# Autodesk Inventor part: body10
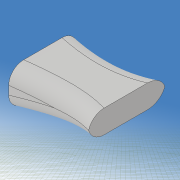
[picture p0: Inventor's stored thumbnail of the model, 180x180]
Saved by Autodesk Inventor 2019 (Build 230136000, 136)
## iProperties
Created: 2020-12
Part Number: body10
Material: 一般
Document SubType Name: Modeling
Designer: kikut
Density: 1 g/cm^3
Appearance: 既定
Mass: 87.6477 g
Surface Area: 156.124 cm^2
Volume: 87.6477 cm^3
Author: kikut
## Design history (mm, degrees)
sketch "スケッチ1"
  geometry: L1 (-100, -20)-(100, -20); L2 (100, -20)-(100, 20); L3 (100, 20)-(-100, 20); L4 (-100, 20)-(-100, -20); L5 (-100, -20)-(100, 20); L6 (100, -20)-(-100, 20); 1 further point
  constraints: 12 end point, 2 midpoint, 2 parallel, 1 horizontal, 1 perpendicular
  dimensions: "d0" = 40 distance of L3.end L1.start; "d1" = 200 distance of L2.end L3.end
extrude "押し出し1" new body sketch "スケッチ1" stored distance "d2" = 60; taper "d3" = 0 deg
sketch "スケッチ2"
  geometry: L1 (0, -60)-(0, 0) reference; L2 (200, -60)-(200, 0) reference; L3 (0, 0)-(200, 0) reference; L4 (200, -60)-(0, -60) reference; L5 (0, -26)-(0, -32); L6 (194, -10)-(194, -13); L7 (194, -13)-(174, -33); L8 (174, -33)-(200, -58); L9 (-20, 20)-(220, 20); L10 (220, 20)-(220, -100); L11 (220, -100)-(-20, -100); L12 (-20, -100)-(-20, 20); 12 further points
  constraints: 16 end point, 4 point on line, 2 parallel, 2 vertical, 1 horizontal, 1 perpendicular, 14 other
  dimensions: "d4" = 32 distance from line of point (32, -12) L1; "d5" = 50 horizontal distance of point (32, -12) point (82, -11); "d6" = 50 horizontal distance of point (132, -17) point (82, -11); "d7" = 12 distance from line of point (32, -12) L3; "d8" = 11 distance from line of point (82, -11) L3; "d10" = 17 distance from line of point (132, -17) L3; "d11" = 26 distance from line of L5.start L3; "d12" = 0 distance from line of point (200, -60) L4; "d13" = 28 distance from line of L5.end L4; "d14" = 12 distance from line of point (28, -48) L4; "d15" = 10 distance from line of point (80, -50) L4; "d16" = 16 distance from line of point (130, -44) L4; "d17" = 28 distance from line of point (28, -48) L1; "d19" = 50 horizontal distance of point (130, -44) point (80, -50); "d20" = 80 distance from line of point (80, -50) L1; "d21" = 6 distance from line of L6.start L2; "d22" = 36 distance from line of point (164, -24) L2; "d23" = 24 distance from line of point (176, -20) L2; "d24" = 10 distance from line of L6.start L3; "d25" = 20 distance from line of point (176, -20) L3; "d26" = 24 distance from line of point (164, -24) L3; "d27" = 40 distance from line of point (160, -40) L2; "d28" = 25 distance from line of point (175, -47.5) L2; "d29" = 12.5 distance from line of point (175, -47.5) L4; "d30" = 20 distance from line of L4 point (160, -40); "d31" = 3 distance of L6.start L6.end; "d32" = 33 distance from line of L7.end L3; "d33" = 26 distance from line of L7.end L2; "d34" = 2 distance of L8.end L2.start; "d35" = 120 distance of L11.end L9.start; "d36" = 240 distance of L10.end L11.end; "d37" = 20 distance between parallel lines of L1 L12; "d38" = 20 distance between parallel lines of L3 L9
extrude "押し出し2" cut sketch "スケッチ2" extent not by distance; stored distance "d39" = 0.02; taper "d40" = 0 deg
sketch "スケッチ8"
  geometry: L1 (-100, -20)-(-100, 20) reference; L2 (100, 20)-(100, -20) reference; L3 (-142.805, 0)-(142.831, 0) reference; L4 (110, 30)-(-110, 30); L5 (-110, 30)-(-110, -30); L6 (-110, -30)-(110, -30); L7 (110, -30)-(110, 30); L8 (110, 30)-(-110, -30); L9 (-110, 30)-(110, -30); L10 (-100, -2)-(-100, 2); L11 (100, -3)-(100, 3); 7 further points
  constraints: 16 end point, 4 point on line, 2 midpoint, 2 parallel, 2 perpendicular, 1 collinear, 1 horizontal, 10 other
  dimensions: "d93" = 2 vertical distance of point (0, 0) L10.end; "d94" = 2 vertical distance of L10.start point (0, 0); "d95" = 35 distance from line of point (-65, -10) L1; "d96" = 0 horizontal distance of point (-65, 10) point (-65, -10); "d97" = 10 vertical distance of point (0, 0) point (-65, -10); "d98" = 10 vertical distance of point (-65, 10) point (0, 0); "d99" = 100 distance from line of point (0, -10) L1; "d100" = 0 horizontal distance of point (0, 10) point (0, -10); "d101" = 10 distance of point (0, -10) point (0, 0); "d102" = 10 distance of point (0, 0) point (0, 10); "d103" = 160 distance from line of point (60, -4) L1; "d104" = 0 horizontal distance of point (60, 4) point (60, -4); "d105" = 4 distance from line of L3 point (60, -4); "d106" = 4 distance from line of L3 point (60, 4); "d107" = 3 distance from line of L11.start L3; "d108" = 3 distance from line of L11.end L3; "d109" = 220 distance of L5.end L6.end; "d110" = 60 distance of L4.end L5.end
extrude "押し出し6" cut sketch "スケッチ8" extent not by distance; stored distance "d111" = 10; taper "d112" = 0 deg
sketch "スケッチ9" dims "d113" = 20, "d114" = 12
  geometry: L1 (-29, -18)-(21, -18); L2 (21, -18)-(21, 22); L3 (21, 22)-(-29, 22); L4 (-29, 22)-(-29, -18); L5 (-29, -18)-(21, 22); L6 (21, -18)-(-29, 22); 2 further points; 1 other entity
  constraints: 12 end point, 2 midpoint, 2 parallel, 1 coincident, 1 horizontal, 1 perpendicular, 2 other
  dimensions: "d115" = 50 distance of L2.end L3.end; "d116" = 40 distance of L1.end L2.end
extrude "押し出し7" cut sketch "スケッチ9" distance "d117" = 150; taper "d118" = 0 deg
fillet "フィレット4" dims "d119" = 4
fillet "フィレット5" dims "d120" = 4
fillet "フィレット6" dims "d121" = 2
node "作業平面2"
sketch "スケッチ10"
  geometry: L1 (0, -41.439)-(0, 38.458) reference; L2 (141.833, 0)-(-140.631, 0) reference; L3 (82.55, 12.983)-(81.45, -4.983); A1 r 9 centre (82, 4) between (82.55, 12.983) and (81.45, -4.983); 1 further point
  constraints: 2 end point, 2 point on circle, 1 centre point
  dimensions: "d123" = 82 distance from line of L1 A1.centre; "d124" = 4 distance from line of L2 A1.centre; "d125" = 9 radius of A1; "d126" = 180 deg dimension on A1.centre L3.end L3.start; "d127" = 90 deg dimension on L3.end point (0, 0) A1.centre
revolve "回転1" sketch "スケッチ10" stored, may be unused: angle "d128" = 90 deg
mirror "ミラー1"
sketch "スケッチ11"
  geometry: L1 (-50, 30)-(-70, 30); L2 (-70, 30)-(-70, -30); L3 (-70, -30)-(-50, -30); L4 (-50, -30)-(-50, 30); L5 (0, -40.648)-(0, 34.486) reference; L6 (140.69, 0)-(-139.196, 0) reference; L7 (120, 53.792)-(-120, 53.792); L8 (-120, 53.792)-(-120, -46.208); L9 (-120, -46.208)-(120, -46.208); L10 (120, -46.208)-(120, 53.792); 1 further point
  constraints: 16 end point, 4 parallel, 2 horizontal, 2 perpendicular, 2 other
  dimensions: "d130" = 20 distance of L1.start L1.end; "d131" = 60 distance of L3.end L1.start; "d132" = 100 distance of L9.end L7.start; "d133" = 240 distance of L7.start L7.end; "d138" = 50 distance between parallel lines of L4 L5
extrude "押し出し8" cut sketch "スケッチ11" stored distance "d134" = 40; taper "d135" = 0 deg
node "ソリッド1"
other parameters: "d122" = -1
